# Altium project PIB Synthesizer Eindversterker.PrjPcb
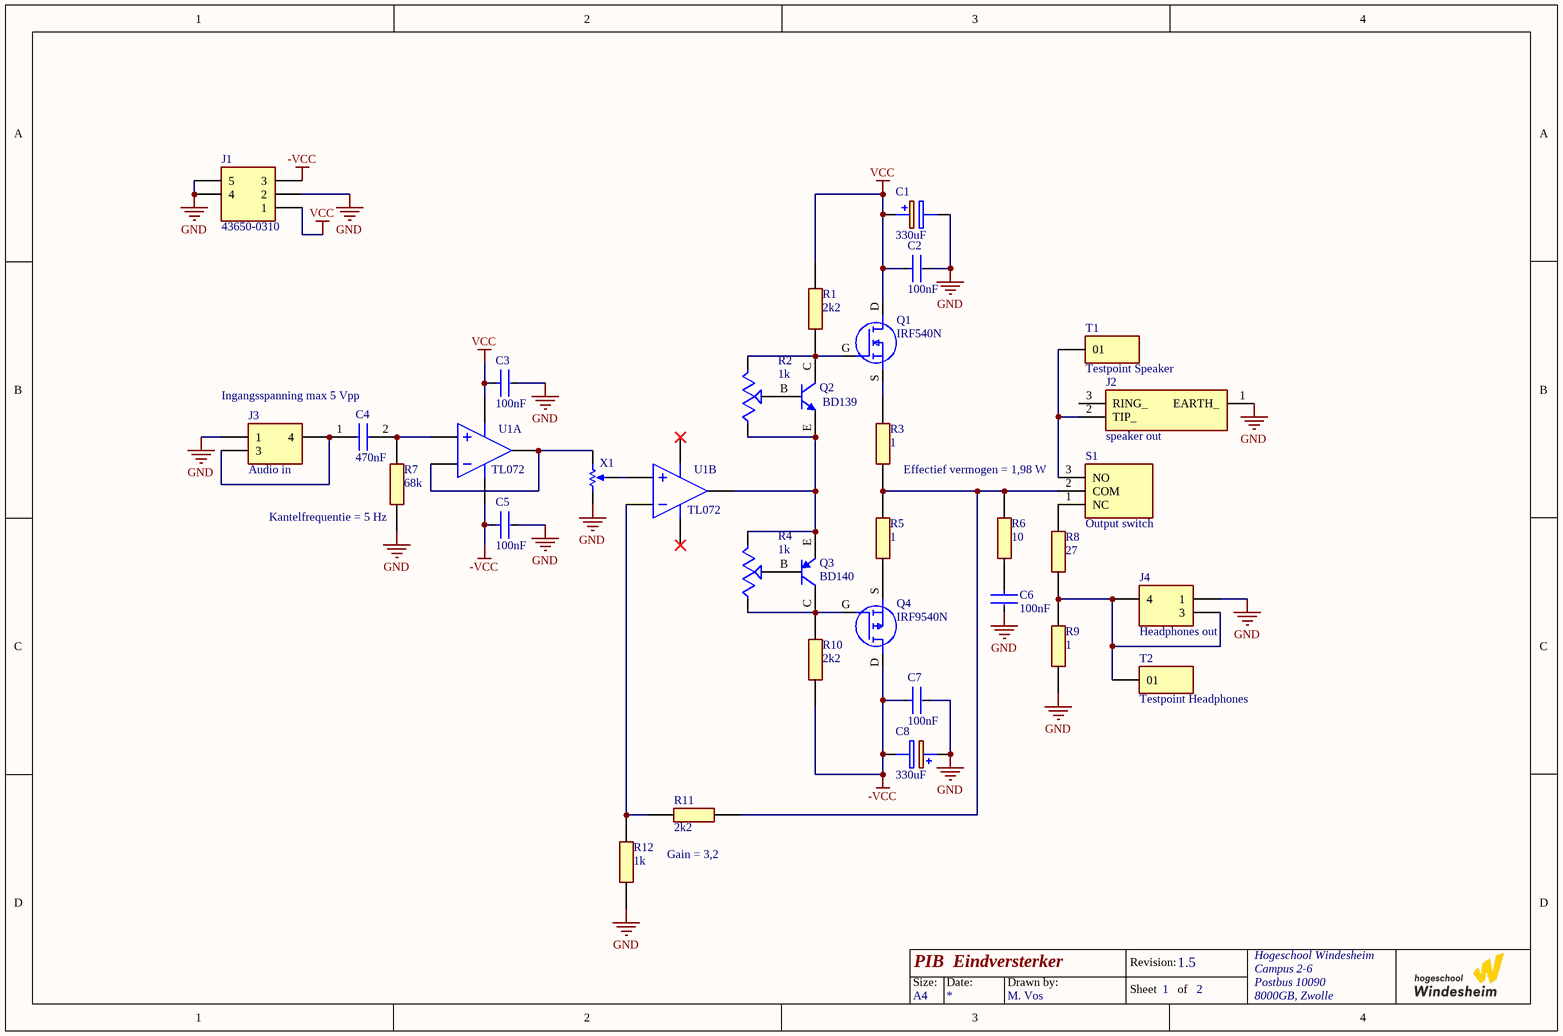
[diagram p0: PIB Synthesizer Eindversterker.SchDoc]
2 sheets, 66 parts. Net scope: global (net labels, ports and power ports of the same name join across sheets).
Board files: PIB Synthesizer Eindversterker.PcbDoc, PIB Synthesizer Voeding.PcbDoc
Sheets:
  PIB Synthesizer Eindversterker.SchDoc
  PIB Synthesizer Voeding.SchDoc

## Sheet PIB Synthesizer Eindversterker.SchDoc: PIB  Eindversterker
size A4; Author: M. Vos; DrawnBy: M. Vos; Organization: Pulse Soundworks; Revision: 1.5; SheetNumber: 1; SheetTotal: 2

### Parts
C1  330uF  [CAPPRD500W65D1000H2200]
C2  100nF  [FP-RDE4K1-MFG]
C3  100nF  [FP-RDE4K1-MFG]
C4  470nF  [MKS4C034702C00JSSD]
C5  100nF  [FP-RDE4K1-MFG]
C6  100nF  [FP-RDE4K1-MFG]
C7  100nF  [FP-RDE4K1-MFG]
C8  330uF  [CAPPRD500W65D1000H2200]
J1  43650-0310  [43650-03YY_091011]
J2  speaker out  [SJ63053A]
J3  Audio in  [ACJSNV353]
J4  Headphones out  [ACJSNV353]
Q1  IRF540N  [TO254P469X1042X1967-3P]
Q2  BD139  [ONSC-TO-225-3-77-09]
Q3  BD140  [ONSC-TO-225-3-77-09]
Q4  IRF9540N  [TO254P469X1042X1967-3P]
R1  2k2  [RESAD1987W56L1031D239]
R2  1k  [TRIM_PTN15-E02SB20]
R3  1  [RESAD1987W56L1031D239]
R4  1k  [TRIM_PTN15-E02SB20]
R5  1  [RESAD1987W56L1031D239]
R6  10  [RESAD1987W56L1031D239]
R7  68k  [RESAD1987W56L1031D239]
R8  27  [RESAD1987W56L1031D239]
R9  1  [RESAD1987W56L1031D239]
R10  2k2  [RESAD1987W56L1031D239]
R11  2k2  [RESAD1987W56L1031D239]
R12  1k  [RESAD1987W56L1031D239]
S1  Output switch  [A107SYCQ04]
T1  Testpoint Speaker  [SAMTEC_MTMM-101-X-X-S-X]  (no BOM)
T2  Testpoint Headphones  [SAMTEC_MTMM-101-X-X-S-X]  (no BOM)
U1A  TL072
U1B  TL072
X1  Potentiometer  (value not drawn)

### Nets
-VCC: C5.1 C7.1 C8.2(-) J1.3 Q4.D R10.1 U1A.4(V+)
GND: C1.2(-) C2.2 C3.2 C5.2 C6.2 C7.2 C8.1(+) J1.2 J1.4 J1.5 J2.1(EARTH_) J3.1 J4.1 R7.1 R9.1 R12.1 X1.1(TOP)
VCC: C1.1(+) C2.1 C3.1 J1.1 Q1.D R1.2 U1A.5(V-)
NetC4_1: C4.1 J3.3 J3.4
NetC4_2: C4.2 R7.2 U1A.2(IN+)
NetC6_1: C6.1 R6.1
NetJ2_2: J2.2(TIP_) S1.3(NO) T1.01
NetJ4_3: J4.3 J4.4 R8.1 R9.2 T2.01
NetQ1_G: Q1.G Q2.C R1.1 R2.3(FINAL)
NetQ1_S: Q1.S R3.2
NetQ2_B: Q2.B R2.2(WIPER)
NetQ2_E: Q2.E Q3.E R2.1(INITIAL) R4.3(FINAL) U1B.3(OUT)
NetQ3_B: Q3.B R4.2(WIPER)
NetQ3_C: Q3.C Q4.G R4.1(INITIAL) R10.2
NetQ4_S: Q4.S R5.1
NetR3_1: R3.1 R5.2 R6.2 R11.2 S1.2(COM)
NetR8_2: R8.2 S1.1(NC)
NetR11_1: R11.1 R12.2 U1B.1(IN-)
NetU1A_1: U1A.1(IN-) U1A.3(OUT) X1.2(BOT)
NetU1B_2: U1B.2(IN+) X1.3(TAP)

Not connected (* = marked no-connect by the designer): J2 3(RING_); U1B 4(V+)* 5(V-)*

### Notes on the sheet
- Ingangsspanning max 5 Vpp
- (near R7) Kantelfrequentie = 5 Hz
- Effectief vermogen = 1,98 W
- Gain = 3,2

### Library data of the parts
C1 C8 = EEU-TP1V331B: Capacitor Polarised; Manufacturer_Name: Panasonic
C2 C3 C5-C7 = CMP-06035-043861-1: Ceramic Capacitor 47nF ±10% 1kV X7R Radial; Lead/Base Style: Formed Leads; Lead Diameter: 0.5mm
C4 = MKS4C034702C00JSSD: Capacitor; Manufacturer_Name: WIMA
J1 = 43650-0310: Connector; Manufacturer_Name: Molex
J2 = SJ-63053A: Connector; Manufacturer_Name: Same Sky
J3 J4 = ACJS-NV35-3: Connector; Manufacturer_Name: Amphenol
Q1 = IRF540N: MOSFET (N-Channel); Manufacturer_Name: Infineon
Q2 = CMP-1048-01271-1: Plastic Medium-Power Silicon NPN Transistor, 3-Pin TO-225, Bulk Box; Manufacturer: On Semiconductor; IC Continuous (A): 1.5
Q3 = CMP-1048-00039-1: Plastic Medium-Power Silicon PNP Transistor, 3-Pin TO-225, Bulk Box; Manufacturer: On Semiconductor; IC Continuous (A): 1.5
Q4 = IRF9540N: MOSFET (P-Channel); Manufacturer_Name: Infineon
R1 R3 R5-R12 = RS01A1R000FE12: Resistor; Manufacturer_Name: Vishay
R2 R4 = PTN15-E02SB20: 15 mm, 2 kÎ©, Vertical, Linear, Screwdriver Shaftless Trimmer Potentiometer; MF: CUI Devices
S1 = A107SYCQ04: Switch; Manufacturer_Name: TE Connectivity
T1 T2 = MTMM-101-X-X-S-X: Connector Header Through Hole 1 position; MF: Samtec; MP: MTMM-101-05-G-S-225
U1A U1B = OpAmp with power terminals: Ideal Operational Amplifier; SimulationGenericComponent: True; GAIN: 1Meg
X1 = Potentiometer: value: 1k; position: 0.5; SimulationGenericComponent: True

## Sheet PIB Synthesizer Voeding.SchDoc: PIB Voeding
size A4; DrawnBy: M. Vos; Revision: 1.1; SheetNumber: 2; SheetTotal: 2
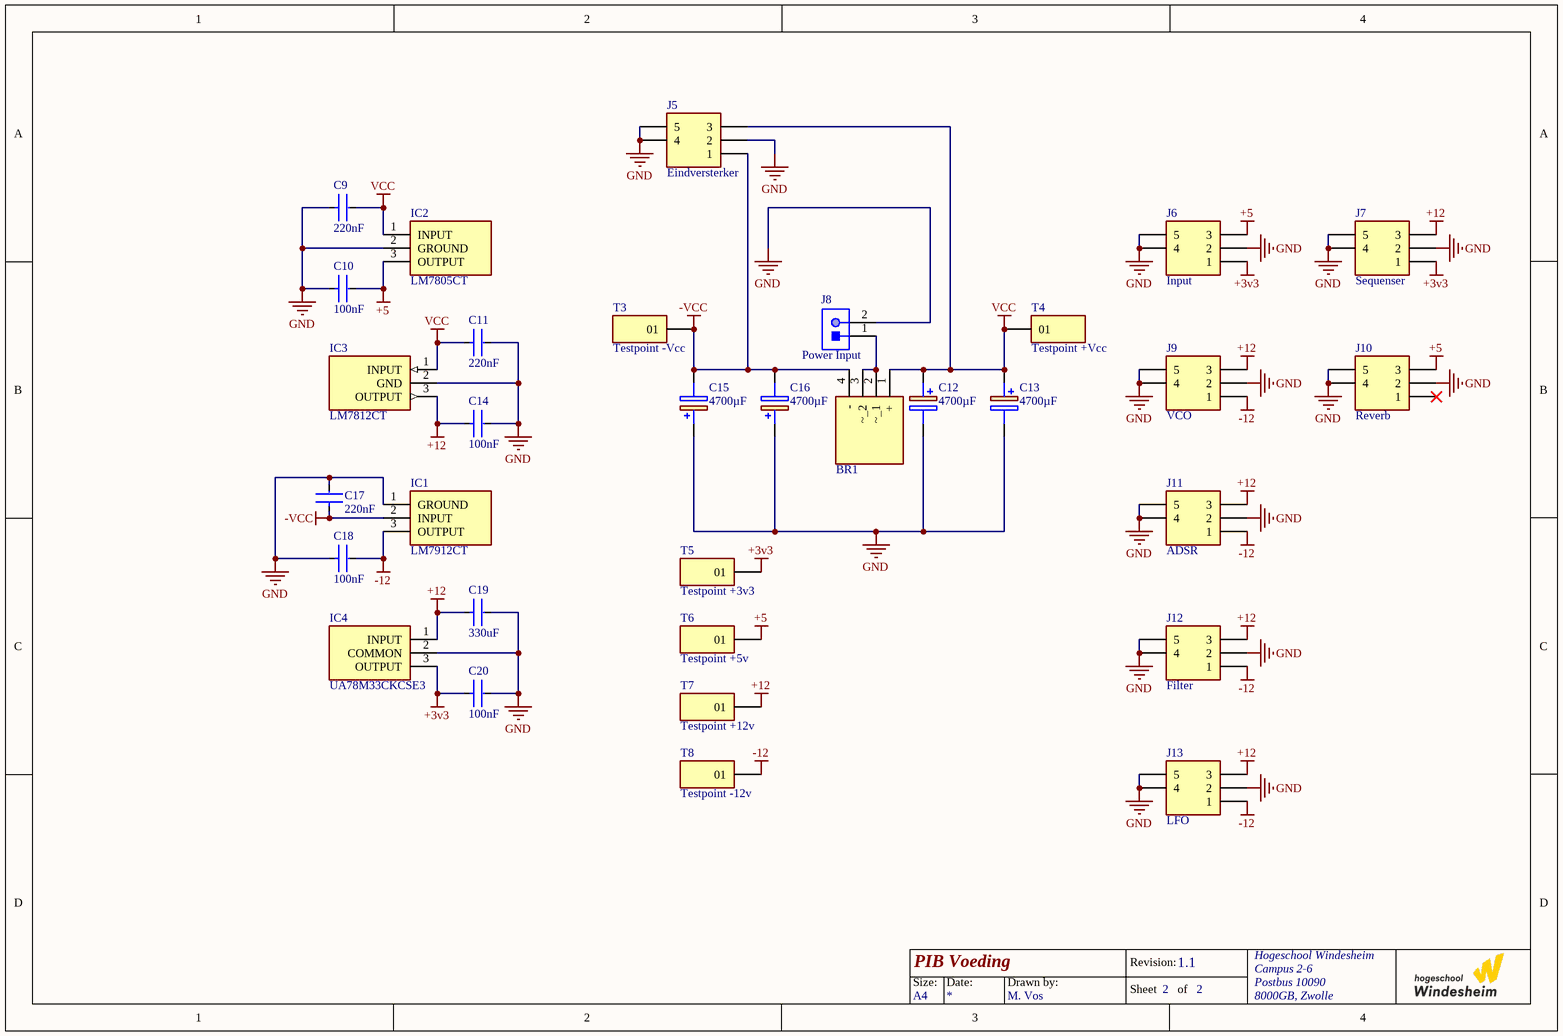
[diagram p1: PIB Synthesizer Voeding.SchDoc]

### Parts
BR1  KBU8B-E4_51  [KBU8BE451]  (value not drawn)
C9  220nF  [FP-RDE4K1-MFG]
C10  100nF  [FP-RDE4K1-MFG]
C11  220nF  [FP-RDE4K1-MFG]
C12  4700µF  [CAPPRD750W82D1800H3750]
C13  4700µF  [CAPPRD750W82D1800H3750]
C14  100nF  [FP-RDE4K1-MFG]
C15  4700µF  [CAPPRD750W82D1800H3750]
C16  4700µF  [CAPPRD750W82D1800H3750]
C17  220nF  [FP-RDE4K1-MFG]
C18  100nF  [FP-RDE4K1-MFG]
C19  330uF  [FP-RDE4K1-MFG]
C20  100nF  [FP-RDE4K1-MFG]
IC1  LM7912CT  [TO254P470X1028X1955-3P]
IC2  LM7805CT  [TO254P470X1028X1955-3P]
IC3  LM7812CT  [TO254P470X1028X1955-3P]
IC4  UA78M33CKCSE3  [TO254P470X1016X1965-3P]
J5  Eindversterker  [43650-03YY_091011]
J6  Input  [43650-03YY_091011]
J7  Sequenser  [43650-03YY_091011]
J8  Power Input  [PHOE-1803277_V]
J9  VCO  [43650-03YY_091011]
J10  Reverb  [43650-03YY_091011]
J11  ADSR  [43650-03YY_091011]
J12  Filter  [43650-03YY_091011]
J13  LFO  [43650-03YY_091011]
T3  Testpoint -Vcc  [SAMTEC_MTMM-101-X-X-S-X]  (no BOM)
T4  Testpoint +Vcc  [SAMTEC_MTMM-101-X-X-S-X]  (no BOM)
T5  Testpoint +3v3  [SAMTEC_MTMM-101-X-X-S-X]  (no BOM)
T6  Testpoint +5v  [SAMTEC_MTMM-101-X-X-S-X]  (no BOM)
T7  Testpoint +12v  [SAMTEC_MTMM-101-X-X-S-X]  (no BOM)
T8  Testpoint -12v  [SAMTEC_MTMM-101-X-X-S-X]  (no BOM)

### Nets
+3v3: C20.1 IC4.3(OUTPUT) J6.1 J7.1 T5.01
+5: C10.2 IC2.3(OUTPUT) J6.3 J10.3 T6.01
+12: C14.1 C19.1 IC3.3(OUTPUT) IC4.1(INPUT) J7.3 J9.3 J11.3 J12.3 J13.3 T7.01
-12: C18.2 IC1.3(OUTPUT) J9.1 J11.1 J12.1 J13.1 T8.01
-VCC: BR1.4(-) C15.2(-) C16.2(-) C17.1 IC1.2(INPUT) J5.1 T3.01
GND: C9.1 C10.1 C11.2 C12.2(-) C13.2(-) C14.2 C15.1(+) C16.1(+) C17.2 C18.1 C19.2 C20.2 IC1.1(GROUND) IC2.2(GROUND) IC3.2(GND) IC4.2(COMMON) J5.2 J5.4 J5.5 J6.2 J6.4 J6.5 J7.2 J7.4 J7.5 J8.2 J9.2 J9.4 J9.5 J10.2 J10.4 J10.5 J11.2 J11.4 J11.5 J12.2 J12.4 J12.5 J13.2 J13.4 J13.5
VCC: BR1.1(+) C9.2 C11.1 C12.1(+) C13.1(+) IC2.1(INPUT) IC3.1(INPUT) J5.3 T4.01
NetBR1_2: BR1.2(~_1) BR1.3(~_2) J8.1

Not connected (* = marked no-connect by the designer): J10 1*

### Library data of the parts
BR1 = KBU8B-E4_51: Bridge Rectifier; Manufacturer_Name: Vishay; Manufacturer_Part_Number: KBU8B-E4/51
C9-C11 C14 C17-C20 = CMP-06035-043861-1: as C2 on sheet PIB Synthesizer Eindversterker
C12 C13 C15 C16 = 860020581026: Capacitor Polarised; Manufacturer_Name: Wurth Elektronik
IC1 = LM7912CT: Undefined or Miscellaneous; Manufacturer_Name: Texas Instruments
IC2 = LM7805CT: Integrated Circuit; Manufacturer_Name: Texas Instruments
IC3 = LM7812CT: Integrated Circuit; Manufacturer_Name: Texas Instruments
IC4 = UA78M33CKCSE3: Integrated Circuit; Manufacturer_Name: Texas Instruments
J5-J7 J9-J13 = 43650-0310: Connector; Manufacturer_Name: Molex
J8 = CMP-002-00014-2: Male Header, Pitch 3.81 mm, 1 x 2 Position, Height 7.25 mm, Tail Length 3.4 mm, RoHS, Bulk; Manufacturer: Phoenix Contact; Voltage Rating: 160V; Current Rating: 8A; Rows: 1
T3-T8 = MTMM-101-X-X-S-X: as T1 on sheet PIB Synthesizer Eindversterker

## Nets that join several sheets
-VCC: PIB Synthesizer Eindversterker (7 pins), PIB Synthesizer Voeding (7 pins)
GND: PIB Synthesizer Eindversterker (17 pins), PIB Synthesizer Voeding (41 pins)
VCC: PIB Synthesizer Eindversterker (7 pins), PIB Synthesizer Voeding (9 pins)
